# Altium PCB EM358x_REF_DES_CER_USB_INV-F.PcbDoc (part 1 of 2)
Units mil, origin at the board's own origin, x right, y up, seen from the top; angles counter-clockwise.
Board outline 2135 x 955 mil, 4 copper layers (Top Layer, Gnd Layer 2, Power Layer 3, Bottom Layer), stack 61.6 mil thick; 69 components, 52 nets, 241 pads, 167 vias.
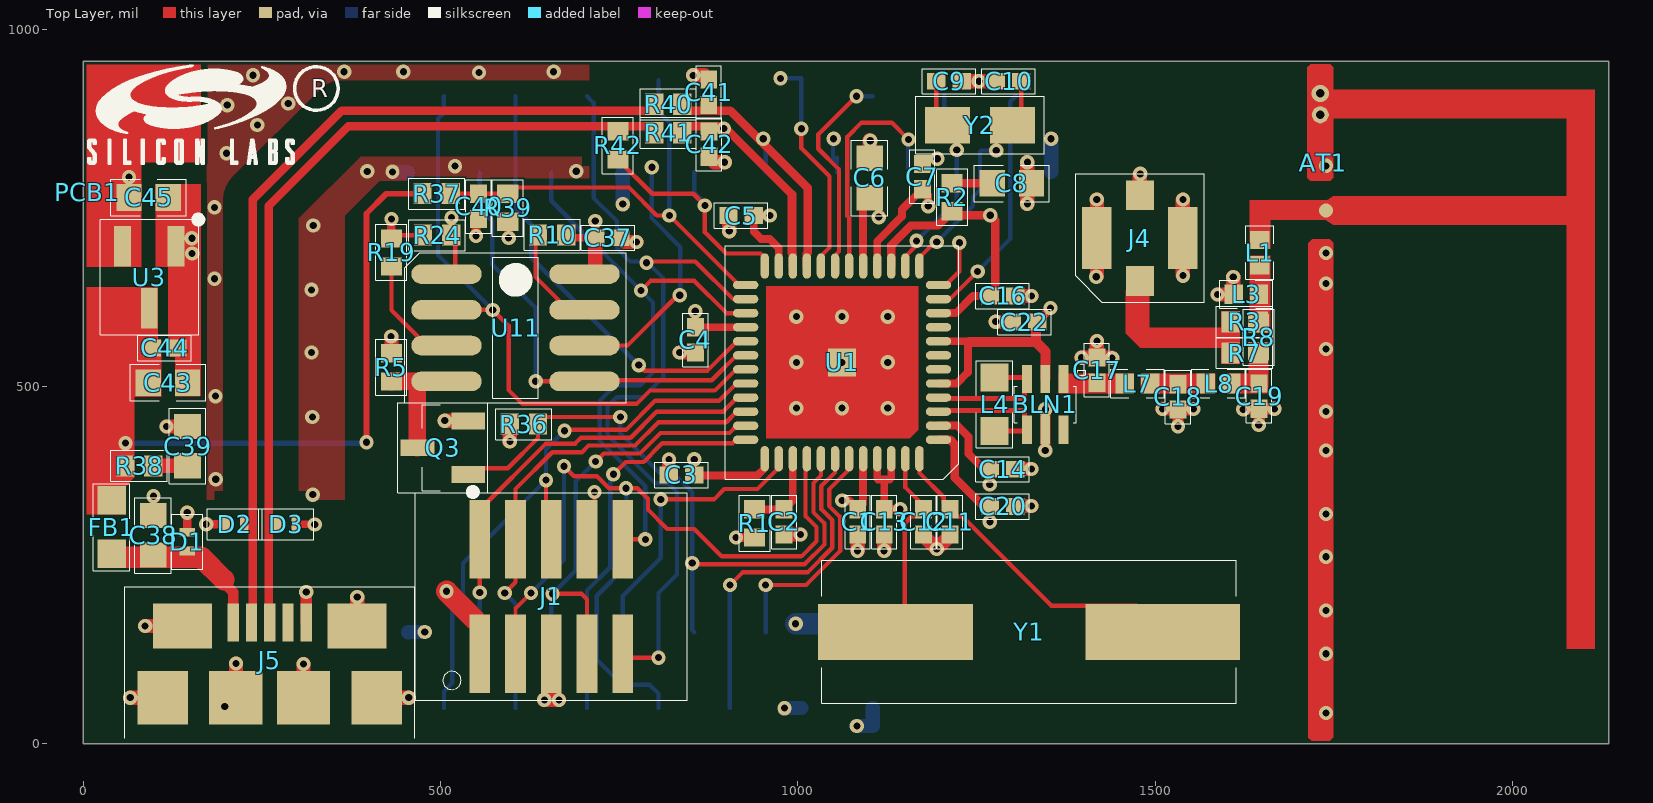
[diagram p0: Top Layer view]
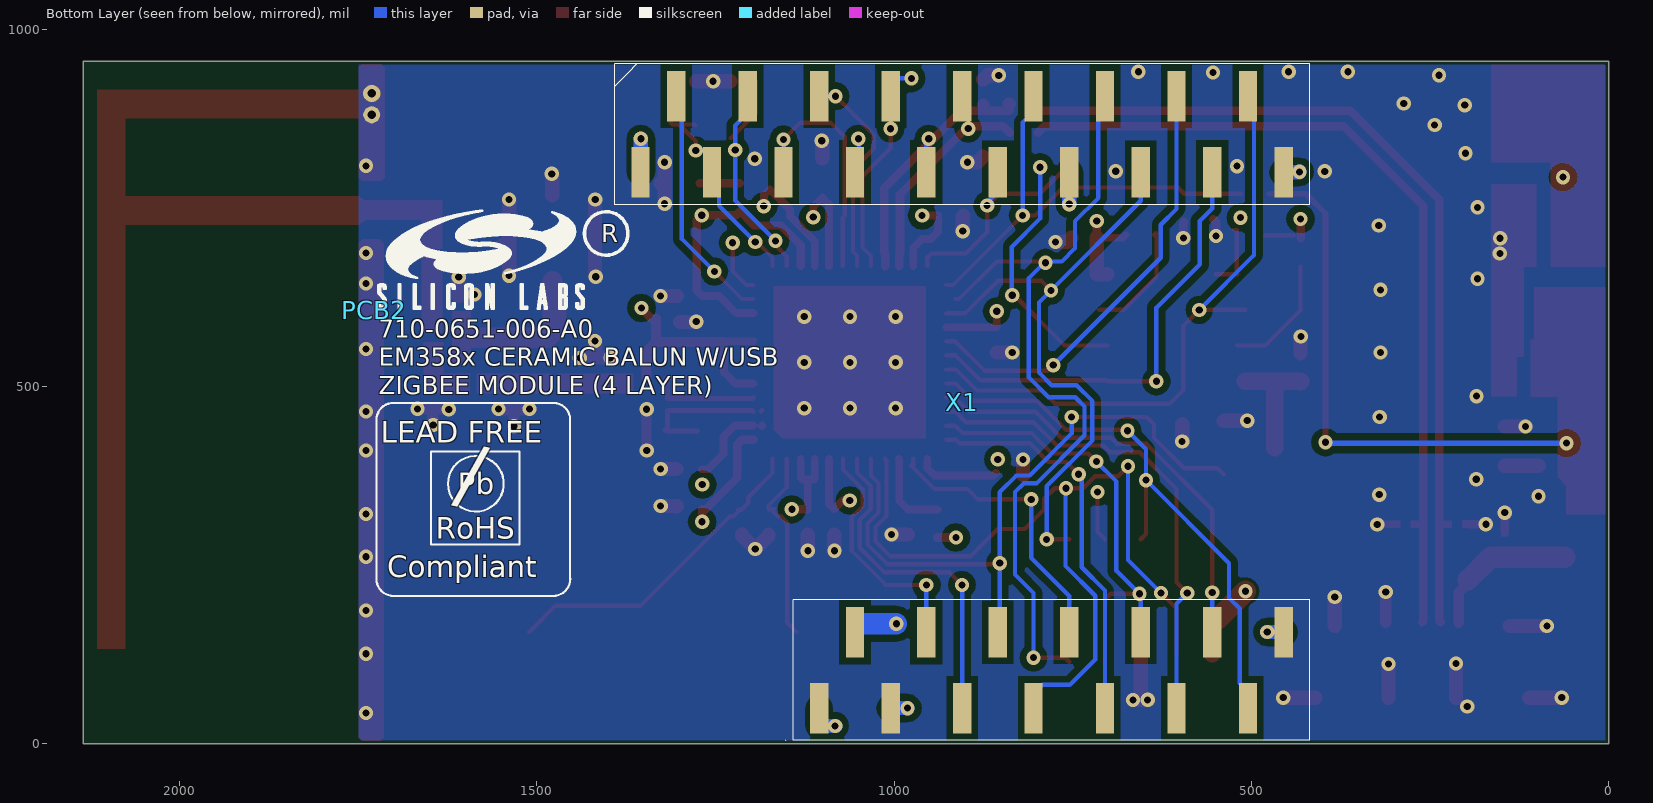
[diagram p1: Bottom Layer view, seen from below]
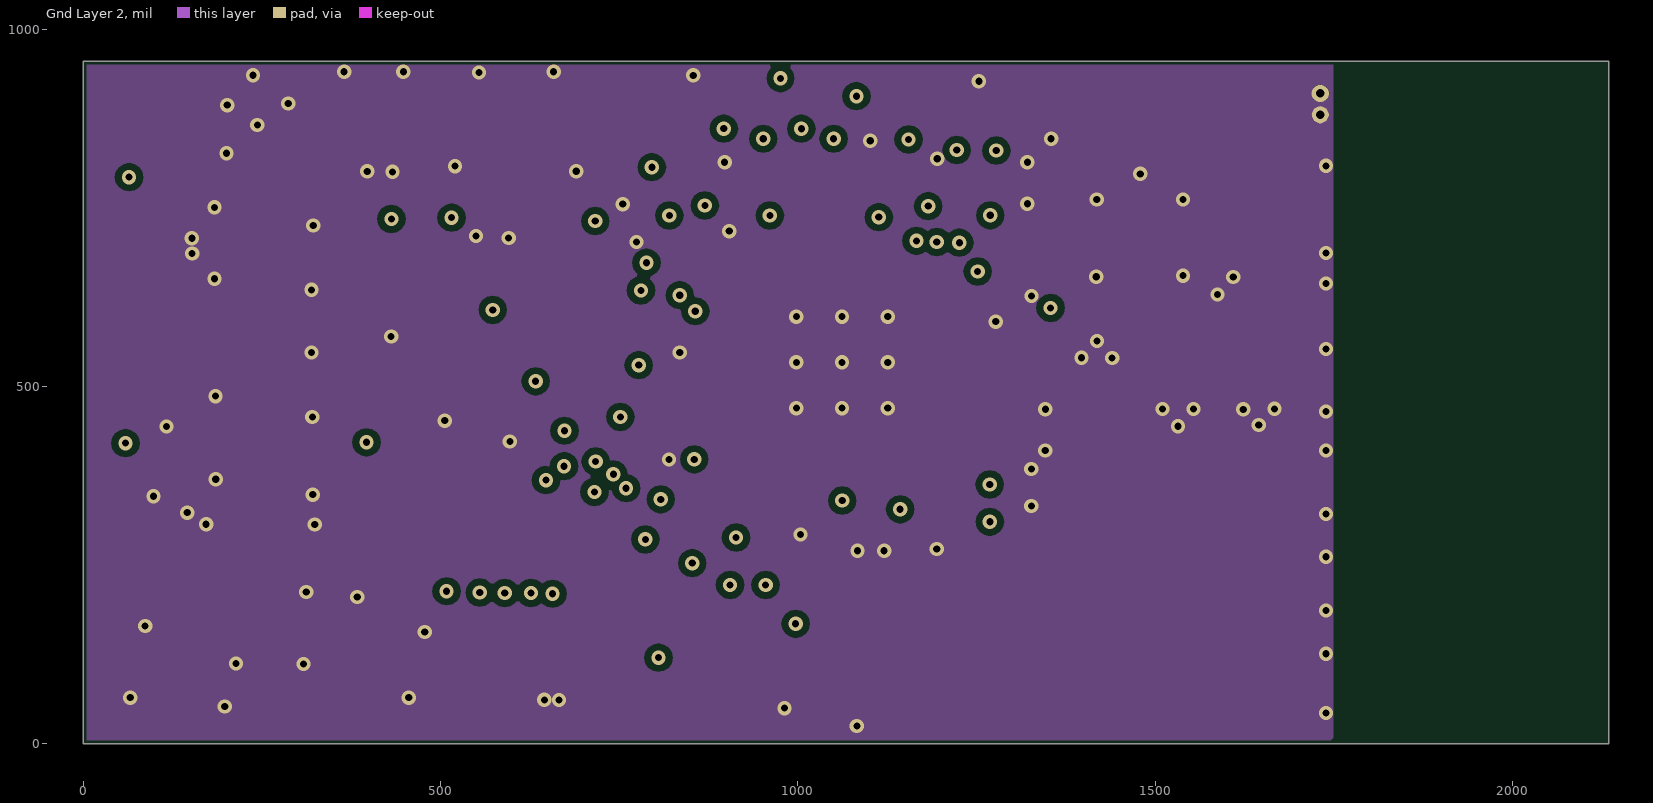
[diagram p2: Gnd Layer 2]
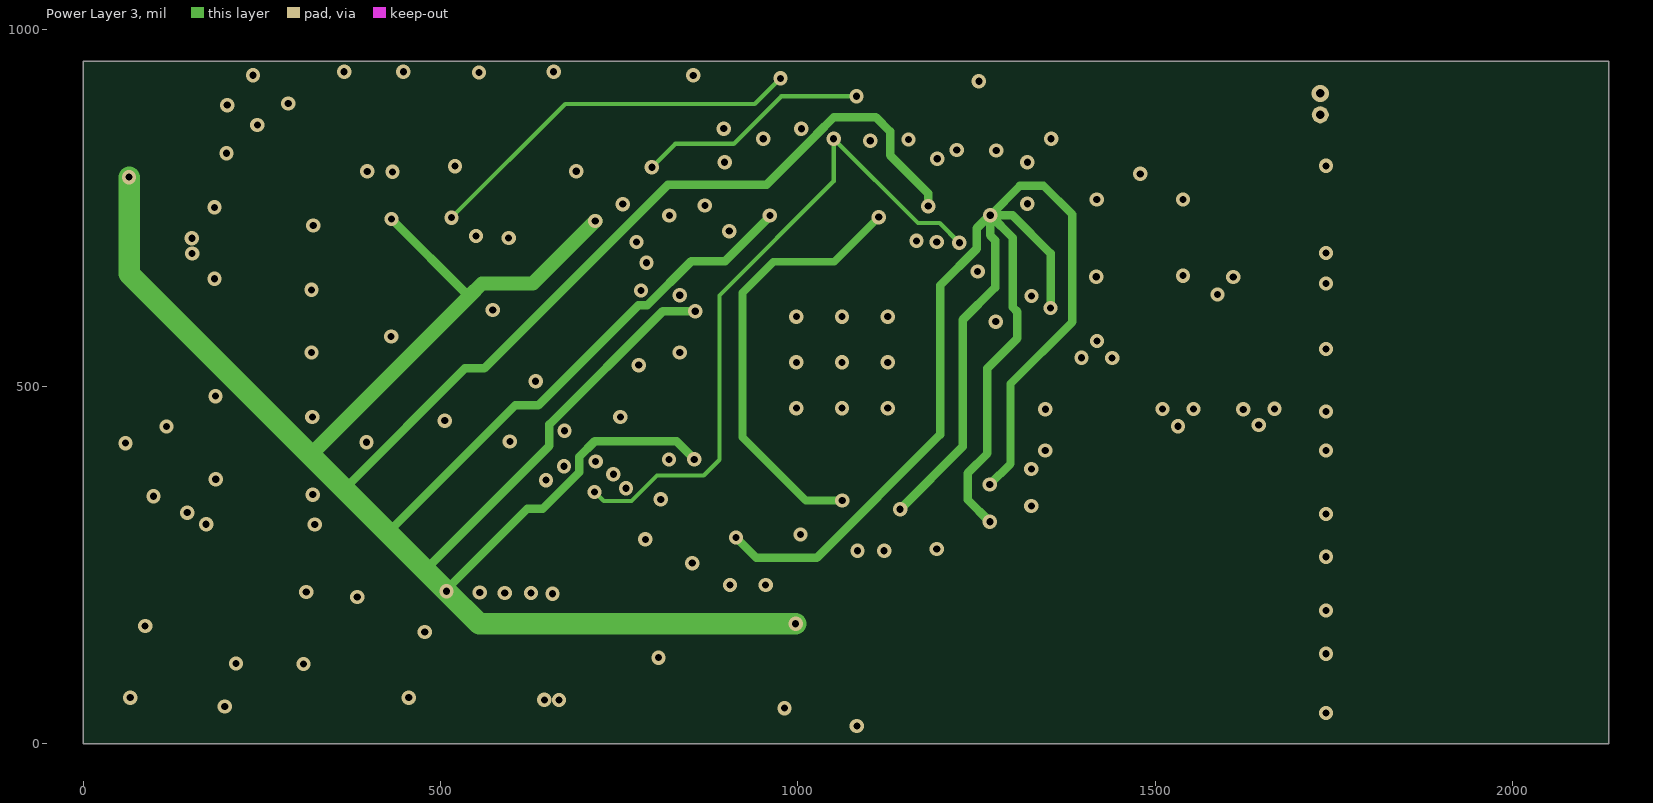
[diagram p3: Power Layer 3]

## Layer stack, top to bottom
Top Solder: solder mask 0.4, Solder Resist, Dk 3.5
Top Layer: signal copper 1.4
Dielectric1: prepreg 16, HR370, Dk 3.9
Gnd Layer 2: signal copper 1.4
Dielectric2: core 24, HR370, Dk 3.9
Power Layer 3: signal copper 1.4
Dielectric3: prepreg 16, HR370, Dk 3.9
Bottom Layer: signal copper 1.4
Bottom Solder: solder mask 0.4, Solder Resist, Dk 3.5

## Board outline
0,0 0,955 2135,955 2135,0

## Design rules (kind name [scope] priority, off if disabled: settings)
AssemblyTestpoint [All] p1: testpointundercomponent=TRUE minsize=30 maxsize=40 preferedsize=40 minholesize=0 maxholesize=10 preferedholesize=10 testpointgrid=1 usegrid=TRUE gridtolerance=0.01 allowsidetop=TRUE allowsidebottom=TRUE
Clearance "D_N - GND" [InNet('D_N') vs (InNet('GND') AND OnLayer('Top Layer') AND InNamedPolygon('USB Shield'))] p1: gap=36 // USB - GND
Clearance "D_P - GND" [InNet('D_P') vs (InNet('GND') AND OnLayer('Top Layer') AND InNamedPolygon('USB Shield'))] p2: gap=36 // USB - GND
Clearance PCB_Only [(InComponentClass('PCB Only')) vs InNet('GND')] p3: gap=0
Clearance "Schematic Clearance Constraint" [InNetClass('R7_Nets')] p4: gap=6
Clearance "Schematic Clearance Constraint_6" [InNet('GND')] p5: gap=9.5
Clearance "Schematic Clearance Constraint_5" [InNetClass('L1_Nets')] p6: gap=6
Clearance "Schematic Clearance Constraint_4" [InNetClass('L7_Nets')] p7: gap=6
Clearance "Schematic Clearance Constraint_3" [InNetClass('L8_Nets')] p8: gap=6
Clearance "Schematic Clearance Constraint_2" [InNetClass('R8_Nets')] p9: gap=6
Clearance "Schematic Clearance Constraint_1" [InNetClass('R3_Nets')] p10: gap=6
Clearance [All] p11: gap=5
ComponentClearance [All] p1: gap=0.1 collisioncheckmode=3 verticalgap=6 showdistances=TRUE
DiffPairsRouting "Schematic Differential Pairs Routing" [InNetClass('R40_Nets')] p1: maxlimit=50 minlimit=8 mostfreqgap=9 toplayer_minwidth=15 toplayer_maxwidth=15 toplayer_prefwidth=15 midlayer1_minwidth=15 midlayer1_maxwidth=15 midlayer1_prefwidth=15 midlayer2_minwidth=15 midlayer2_maxwidth=15 midlayer2_prefwidth=15 bottomlayer_minwidth=15 bottomlayer_maxwidth=15 bottomlayer_prefwidth=15 maxuncoupledlength=500
DiffPairsRouting "Schematic Differential Pairs Routing_1" [InNetClass('R41_Nets')] p2: maxlimit=50 minlimit=8 mostfreqgap=9 toplayer_minwidth=15 toplayer_maxwidth=15 toplayer_prefwidth=15 midlayer1_minwidth=15 midlayer1_maxwidth=15 midlayer1_prefwidth=15 midlayer2_minwidth=15 midlayer2_maxwidth=15 midlayer2_prefwidth=15 bottomlayer_minwidth=15 bottomlayer_maxwidth=15 bottomlayer_prefwidth=15 maxuncoupledlength=500
DiffPairsRouting [All] p3: maxlimit=10 minlimit=10 mostfreqgap=10 toplayer_minwidth=15 toplayer_maxwidth=15 toplayer_prefwidth=15 midlayer1_minwidth=15 midlayer1_maxwidth=15 midlayer1_prefwidth=15 midlayer2_minwidth=15 midlayer2_maxwidth=15 midlayer2_prefwidth=15 bottomlayer_minwidth=15 bottomlayer_maxwidth=15 bottomlayer_prefwidth=15 maxuncoupledlength=500
FabricationTestpoint [All] p1: side=3 testpointundercomponent=TRUE minsize=30 maxsize=40 preferedsize=40 minholesize=0 maxholesize=10 preferedholesize=10 testpointgrid=1 allowsidetop=TRUE allowsidebottom=TRUE usegrid=TRUE gridtolerance=0.01
HoleSize [All] p1: absolutevalues=TRUE maxlimit=100 minlimit=10 maxpercent=80.000 minpercent=20.000
MatchedLengths "Schematic Matched Net Lengths_2" [InNetClass('R40_Nets')] p1: tolerance=100 checknetsindiffpair=TRUE checkdiffpairvsdiffpair=FALSE checkothers=FALSE
MatchedLengths "Schematic Matched Net Lengths_1" [InNetClass('R41_Nets')] p2: tolerance=100 checknetsindiffpair=TRUE checkdiffpairvsdiffpair=FALSE checkothers=FALSE
MatchedLengths "Schematic Matched Net Lengths" [InNetClass('L4_Nets')] p3: tolerance=2.5 checknetsindiffpair=TRUE checkdiffpairvsdiffpair=FALSE checkothers=FALSE
MinimumSolderMaskSliver [All] p1: minsoldermaskwidth=2
PlaneClearance [All] p1: clearance=10
PlaneConnect [All] p1: planeconnectstyle=Direct reliefexpansion=20 reliefentries=4 reliefconductorwidth=10 reliefairgap=10
PolygonConnect PolygonConnect_4 [All vs IsNamedPolygon('Top Layer-No Net')] p1: connectstyle=Relief reliefconductorwidth=10 reliefentries=4 polygonreliefangle="90 Angle" airgapwidth=10
PolygonConnect PolygonConnect_3 [All vs IsNamedPolygon('GROUND')] p2: connectstyle=Direct reliefconductorwidth=10 reliefentries=4 polygonreliefangle="90 Angle" airgapwidth=10
PolygonConnect PolygonConnect_2 [All vs IsNamedPolygon('GROUND')] p3: connectstyle=Direct reliefconductorwidth=10 reliefentries=4 polygonreliefangle="90 Angle" airgapwidth=10
PolygonConnect PolygonConnect_1 [All vs IsNamedPolygon('GROUND')] p4: connectstyle=Relief reliefconductorwidth=10 reliefentries=4 polygonreliefangle="90 Angle" airgapwidth=10
PolygonConnect [All] p5: connectstyle=Direct reliefconductorwidth=10 reliefentries=4 polygonreliefangle="90 Angle" airgapwidth=10
RoutingVias [All] p1: holewidth=10 width=20 viastyle="Through Hole" minholewidth=10 minwidth=20 maxholewidth=10 maxwidth=40
ShortCircuit ShortCircuit_1 [InNet('NetAT1_1') vs InNet('GND')] p1: allowed=TRUE
ShortCircuit [All] p2: allowed=FALSE
ShortCircuit "Schematic Short-Circuit Constraint" [InNet('GND')] p3: allowed=TRUE
SilkToSilkClearance SilkToSilkClearance_1 [(InComponentClass('PCB Only')) vs (InComponentClass('PCB Only'))] p1: silktosilkclearance=0
SilkToSilkClearance SilkToSilkClearance_2 [InComponent('U11')] p2: silktosilkclearance=0
SilkToSilkClearance [All] p3: silktosilkclearance=0.1
SilkToSolderMaskClearance SilkscreenOverComponentPads [IsPad] p1: minsilkscreentomaskgap=0.1 clearancetoexposedcopper=TRUE
SolderMaskExpansion [All] p1: expansion=1
Width "Schematic Width Constraint_2" [InNetClass('R40_Nets')] p1: maxlimit=60 minlimit=6 preferedwidth=12
Width "Schematic Width Constraint_3" [InNetClass('R41_Nets')] p2: maxlimit=60 minlimit=6 preferedwidth=12
Width "Schematic Width Constraint_1" [InNetClass('R7_Nets')] p3: maxlimit=60 minlimit=6 preferedwidth=28
Width "Schematic Width Constraint_14" [InNetClass('C22_Nets')] p4: maxlimit=40 minlimit=5 preferedwidth=20
Width "Schematic Width Constraint_13" [InNetClass('C6_Nets')] p5: maxlimit=40 minlimit=5 preferedwidth=20
Width "Schematic Width Constraint_12" [InNetClass('C45_Nets')] p6: maxlimit=40 minlimit=5 preferedwidth=20
Width "Schematic Width Constraint_11" [InNetClass('L1_Nets')] p7: maxlimit=60 minlimit=6 preferedwidth=28
Width "Schematic Width Constraint_10" [InNetClass('L7_Nets')] p8: maxlimit=60 minlimit=6 preferedwidth=28
Width "Schematic Width Constraint_9" [InNetClass('L8_Nets')] p9: maxlimit=60 minlimit=6 preferedwidth=28
Width "Schematic Width Constraint_8" [InNetClass('R8_Nets')] p10: maxlimit=60 minlimit=6 preferedwidth=28
Width "Schematic Width Constraint_7" [InNetClass('R3_Nets')] p11: maxlimit=60 minlimit=6 preferedwidth=28
Width "Schematic Width Constraint" [InNetClass('L4_Nets')] p12: maxlimit=10 minlimit=5 preferedwidth=7
Width [All] p13: maxlimit=40 minlimit=4 preferedwidth=5
18 further rules are at their usual default settings.

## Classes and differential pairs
net class R39_Nets: GND PA3
net class R38_Nets: NetC39_1 VBUS
net class D1_Nets: GND NetC38_1
net class C43_Nets: GND VBUS
net class C39_Nets: GND NetC39_1
net class C38_Nets: GND NetC38_1
net class Y2_Nets: PC6 PC7
net class Y1_Nets: OSCA OSCB
net class X1_Nets: GND JCLK NRESET PA01_D_N PA01_D_P PA2 PA3 PA4 PA5 PA6 PA7 PB0 PB1 PB2 PB3 PB4 PB5 PB6 PB7 PC0 PC1 PC2 PC3 PC4 PC5 PC6 PC7 VBRD
net class U11_Nets: NSF_GND NSF_HOLD NSF_WP PB1 PB2 PB3 PB4 VBRD
net class U3_Nets: GND NetU3_4 VBRD VBUS
net class U1_Nets: 1V2_CORE 1V8 GND JCLK NetC2_1 NetU1_9 NRESET OSCA OSCB PA01_D_N PA01_D_P PA2 PA3 PA4 PA5 PA6 PA7 PB0 PB1 PB2 PB3 PB4 PB5 PB6 PB7 PC0 PC1 PC2 PC3 PC4 PC5 PC6 PC7 RF_N RF_P TX_ALT_N TX_ALT_P VBRD
net class C44_Nets: GND VBUS
net class R42_Nets: D_P PA2
net class R41_Nets: D_P PA01_D_P
net class R40_Nets: D_N PA01_D_N
net class C40_Nets: GND PA3
net class R37_Nets: PA3 VBUS
net class R36_Nets: GND PB7
net class R24_Nets: PB4 VBRD
net class R19_Nets: NSF_WP VBRD
net class R10_Nets: NSF_HOLD VBRD
net class R8_Nets: NetC19_1 NetL1_1
net class R7_Nets: NetC19_1 NetJ4_1
net class R5_Nets: GND NSF_GND
net class R3_Nets: NetJ4_1 NetL1_1
net class R2_Nets: 1V8 NetC8_1
net class R1_Nets: 1V8 NetC2_1
net class Q3_Nets: GND NSF_GND PB7
net class L8_Nets: NetC18_1 NetC19_1
net class L7_Nets: NetBLN1_1 NetC18_1
net class L4_Nets: RF_N RF_P
net class L3_Nets: GND NetL1_1
net class L1_Nets: NetAT1_1 NetL1_1
net class J5_Nets: D_N D_P GND NetC38_1 NetJ5_4
net class J4_Nets: GND NetJ4_1
net class J1_Nets: GND JCLK NRESET PA4 PA5 PC0 PC2 PC3 PC4 VBRD
net class FB1_Nets: NetC38_1 VBUS
net class D3_Nets: D_P GND
net class D2_Nets: D_N GND
net class C45_Nets: GND VBRD
net class C42_Nets: GND PA01_D_P
net class C41_Nets: GND PA01_D_N
net class C37_Nets: GND VBRD
net class C22_Nets: 1V8 GND
net class C20_Nets: 1V8 GND
net class C19_Nets: GND NetC19_1
net class C18_Nets: GND NetC18_1
net class C17_Nets: GND NetBLN1_1
net class C16_Nets: 1V8 GND
net class C14_Nets: 1V8 GND
net class C13_Nets: 1V8 GND
net class C12_Nets: GND OSCB
net class C11_Nets: GND OSCA
net class C10_Nets: GND PC6
net class C9_Nets: GND PC7
net class C8_Nets: GND NetC8_1
net class C7_Nets: GND VBRD
net class C6_Nets: 1V2_CORE GND
net class C5_Nets: GND VBRD
net class C4_Nets: GND VBRD
net class C3_Nets: GND VBRD
net class C2_Nets: GND NetC2_1
net class C1_Nets: 1V2_CORE GND
net class BLN1_Nets: 1V8 GND NetBLN1_1 NetBLN1_6 RF_N RF_P
net class AT1_Nets: GND NetAT1_1
component class "PCB Only": AT1 PCB1 PCB2
differential pair D: +D_P -D_N
differential pair PA01_D: +PA01_D_P -PA01_D_N
differential pair RF: +RF_P -RF_N

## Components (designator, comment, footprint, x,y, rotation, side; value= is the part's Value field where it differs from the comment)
AT1 "Copper Trace" INVERTED_F_062_SM 1749.2,746 r90 top
BLN1 "CHIP MULTILAYER CERAMIC, 2.4 GHZ. 50/100 Ohm" BLN_0805 1372,510 r0 top
C1 "10NF" C_0402 1084,328 r180 top
C2 "0.47uF" C_0402 981,328 r180 top
C3 "0.1uF" C_0402 855,376 r90 top
C4 "0.1uF" C_0402 856.8,582.7 r180 top
C5 "0.1uF" C_0402 938.4,738.9 r90 top
C6 "1.0uF" C_0603 1100.6,764 r90 top
C7 "0.1uF" C_0402 1174.3,775.76 r0 top
C8 "2.2uF" C_0603 1272,784 r0 top
C9 "33pF, (DNI)" C_0402 1193.99,926.94 r270 top
C10 "22PF, (DNI)" C_0402 1312.87,926.94 r90 top
C11 "22PF" C_0402 1213,328 r180 top
C12 "22PF" C_0402 1176,328 r180 top
C13 "10pF" C_0402 1121,328 r180 top
C14 "10NF" C_0402 1269,384 r270 top
C16 "10NF" C_0402 1269,626.5 r270 top
C17 "1pF" C_0402 1418.5,504.9 r0 top
C18 "1.8pF" C_0402 1532.1,502.9 r180 top
C19 "1pF" C_0402 1645.6,503.9 r180 top
C20 "10NF" C_0402 1269,332 r270 top
C22 "10pF" C_0402 1335,590 r90 top
C37 "10NF, (DNI)" C_0402 716.62,707.87 r270 top
C38 "1.0uF" C_0603 98,264 r90 top
C39 "4.7uF" C_0603 146.07,388.76 r90 top
C40 "1.0uF, (DNI)" C_0402 553.4,769.49 r180 top
C41 "33pF" C_0402 875.5,893.8 r0 top
C42 "33pF" C_0402 876,856.5 r180 top
C43 "DNI" C_0603 90.95,505.03 r0 top
C44 "10NF, (DNI)" C_0402 96.35,553.65 r270 top
C45 "1.0uF, (DNI)" C_0603 64.01,764.3 r0 top
D1 "TVS" TVS_0402 145.63,282.5 r270 top (schematic designator D2)
D2 "TVS" TVS_0402 212.4,307 r0 top
D3 "TVS" TVS_0402 284.4,307 r180 top
FB1 "60Ohm 100MHz" L_0603 40,265.67 r180 top
J1 "FTSH-105-01-F-DV-K, (DNI)" 610-0019-000-REF-DES 555,126 r270 top
J4 "U.FL, (DNI)" UFL-R-SMT_1 1478.7,707.4 r180 top
J5 "10118192-0001LF" FCI_10118192-0001LF 261.07,169.61 r0 top
L1 "2.0nH" L_0402 1646.4,669.36 r90 top
L3 "1.5nH" L_0402 1645.4,628.7 r180 top
L4 "3.9nH" L_0603 1275.5,512.3 r0 top
L7 "2.7nH" L_0402 1457.66,503.9 r0 top
L8 "2.7nH" L_0402 1571.1,503.9 r0 top
LOGO1 "SiliconLabsLogo_100" SiliconLabsLogo_100_Mech-16 3677,-1889.5 r0 top
PCB1 "EM35x Ceramic Balun 4 Layer Reference Design w/USB, Inverted F, Corporate Logo" 710-0651-006 5.5,771.4 r0 top
PCB2 "Bottom Silk Screen ID and RoHS Text" 710-0651-006_ROHS 1727.5,606.7 r180 bottom
Q3 "2N7002, (DNI)" SOT23-3L 503.4,414.1 r180 top
R1 "10 Ohm" R_0402 939.7,288.4 r90 top
R2 "1 Ohm" R_0402 1216,745 r90 top
R3 "0_OHM, (DNI)" R_0402 1645,590.1 r180 top
R5 "0_OHM, (DNI)" R_0402 431.4,506.7 r90 top
R7 "0_OHM, (DNI)" R_0402 1645,546.6 r180 top
R8 "0_OHM" R_0402 1645,548.73 r90 top
R10 "100K, (DNI)" R_0402 636.57,711.94 r0 top
R19 "100K, (DNI)" R_0402 431.4,667.63 r90 top
R24 "100K, (DNI)" R_0402 515,711.5 r180 top
R36 "100K, (DNI)" R_0402 636.37,447 r180 top
R37 "100K" R_0402 474.97,769.58 r0 top
R38 "0.51 ohm" R_0402 98.11,388.76 r180 top
R39 "150K" R_0402 594.1,769.58 r270 top
R40 "33 Ohm" R_0402 799,894.75 r0 top
R41 "33 Ohm" R_0402 799,854.78 r0 top
R42 "1.5k" R_0402 748.21,856.81 r270 top
U1 "EM358x" EM357 1062,533.5 r0 top
U3 "LDO, (DNI)" TSOP95P280X90-3N 92.5,652.65 r270 top
U11 "8M, (DNI)" SOIC127P600-8M 605,582 r0 top
X1 "Dual Row Socket, (DNI)" EM35X_RCM_MODULE_SIDE_SMT 1355,852.85 r180 bottom locked
Y1 "24.000MHZ, 18PF LOAD" HC-49-SMD 1323.73,156.33 r180 top
Y2 "32.768KHz, 12.5pF, (DNI)" IL3X 1254.93,865.44 r180 top

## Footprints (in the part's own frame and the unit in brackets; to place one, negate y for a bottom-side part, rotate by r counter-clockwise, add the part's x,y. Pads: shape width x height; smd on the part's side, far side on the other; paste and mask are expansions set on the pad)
610-0019-000-REF-DES [mil] "old footprint with keepout for cable connector"
  rect 110x29 smd: 1(0,0) 2(-160,0) 3(0,50) 4(-160,50) 5(0,100) 6(-160,100) 7(0,150) 8(-160,150) 9(0,200) 10(-160,200)
  silkscreen extent -225,-90 65,290, body extent -148,-25 -12,225, height 225
710-0651-006 [mil] "EM35x Ceramic Balun W/USB W/Inverted F"
  silkscreen extent 1,40 351,178
710-0651-006_ROHS [mil] "EM35x CERAMIC BALUN W/USB W/Inverted F"
  silkscreen extent 3,-400 355,139
BLN_0805 [mm]
  rect 0.35x1 smd: 1(0,0) 2(-0.65,0) 3(-1.3,0) 4(-1.3,-1.8) 5(-0.65,-1.8) 6(0,-1.8)
  silkscreen extent -1.75,-1.55 0.78,0.31
C_0402 [mm]
  rect 0.6x0.65 smd mask+0.051: 1(0,0) 2(0,0.9)
  silkscreen extent -0.45,-0.5 0.45,1.4, body extent -0.28,-0.05 0.28,0.97, height 1.02
C_0603 [mm]
  rect 0.9x0.95 smd mask+0.051: 1(0,0) 2(1.4,0)
  silkscreen extent -0.64,-0.65 2.04,0.65, body extent -0.09,-0.39 1.51,0.39, height 0.89
EM35X_RCM_MODULE_SIDE_SMT [mm]
  rect 0.65x1.8 smd: 1(0,-1.35) 2(1.27,1.35) 3(2.54,-1.35) 4(3.81,1.35) 5(5.08,-1.35) 6(6.35,1.35) 7(7.62,-1.35) 8(8.89,1.35) 9(10.16,-1.35) 10(11.43,1.35) 11(12.7,-1.35) 12(13.97,1.35) 13(15.24,-1.35) 14(16.51,1.35) 15(17.78,-1.35) 16(19.05,1.35) 17(20.32,-1.35) 18(21.59,1.35) 19(22.86,-1.35) 20(22.86,-17.7) 21(21.59,-20.4) 22(20.32,-17.7) 23(19.05,-20.4) 24(17.78,-17.7) 25(16.51,-20.4) 26(15.24,-17.7) 27(13.97,-20.4) 28(12.7,-17.7) 29(11.43,-20.4) 30(10.16,-17.7) 31(8.89,-20.4) 32(7.62,-17.7) 33(6.35,-20.4)
  silkscreen extent -0.93,-21.56 23.78,2.5
EM357 [mm]
  oval 0.9x0.3 smd paste+0 mask+0: 1(3.425,-2.75) 2(3.425,-2.25) 3(3.425,-1.75) 4(3.425,-1.25) 5(3.425,-0.75) 6(3.425,-0.25) 7(3.425,0.25) 8(3.425,0.75) 9(3.425,1.25) 10(3.425,1.75) 11(3.425,2.25) 12(3.425,2.75) 25(-3.425,2.75) 26(-3.425,2.25) 27(-3.425,1.75) 28(-3.425,1.25) 29(-3.425,0.75) 30(-3.425,0.25) 31(-3.425,-0.25) 32(-3.425,-0.75) 33(-3.425,-1.25) 34(-3.425,-1.75) 35(-3.425,-2.25) 36(-3.425,-2.75)
  oval 0.3x0.9 smd paste+0 mask+0: 13(2.75,3.425) 14(2.25,3.425) 15(1.75,3.425) 16(1.25,3.425) 17(0.75,3.425) 18(0.25,3.425) 19(-0.25,3.425) 20(-0.75,3.425) 21(-1.25,3.425) 22(-1.75,3.425) 23(-2.25,3.425) 24(-2.75,3.425) 37(-2.75,-3.425) 38(-2.25,-3.425) 39(-1.75,-3.425) 40(-1.25,-3.425) 41(-0.75,-3.425) 42(-0.25,-3.425) 43(0.25,-3.425) 44(0.75,-3.425) 45(1.25,-3.425) 46(1.75,-3.425) 47(2.25,-3.425) 48(2.75,-3.425)
  rect 1x1 smd paste-1 mask+0: 49(0,0)
  Top Layer region: 2.7,-2.4 2.4,-2.7 -2.7,-2.7 -2.7,2.7 2.7,2.7
  Top Layer pour cut-out: 3.506,-3.505 3.046,-3.505 3.046,-3.045 3.506,-3.045 3.506,-3.505
  Top Layer pour cut-out: 3.507,3.04 3.047,3.04 3.047,3.5 3.507,3.5 3.507,3.04
  Top Layer pour cut-out: -3.039,3.04 -3.499,3.04 -3.499,3.5 -3.039,3.5 -3.039,3.04
  Top Layer pour cut-out: -3.039,-3.503 -3.499,-3.503 -3.499,-3.043 -3.039,-3.043 -3.039,-3.503
  silkscreen extent -4.15,-4.15 4.15,4.15, body extent -3.51,-3.51 3.51,3.51, height 0.9
FCI_10118192-0001LF [mm] "USB Connector - Surface Mount"
  rect 0.4x1.35 smd mask+0.076: 1(-1.3,0) 2(-0.65,0) 3(0,0) 4(0.65,0) 5(1.3,0)
  rect 2.1x1.6 smd mask+0.076: 6(3.1,-0.125) 11(-3.1,-0.125)
  rect 1.8x1.9 smd mask+0.076: 7(3.8,-2.675) 10(-3.8,-2.675)
  rect 1.9x1.9 smd mask+0.076: 8(1.2,-2.675) 9(-1.2,-2.675)
  silkscreen extent -5.15,-4.13 5.15,1.26, body extent -4.16,-5.69 4.16,0.35, height 3
HC-49-SMD [mm]
  rect 5.5x2 smd: 1(-4.75,0) 2(4.75,0)
  silkscreen extent -7.37,-2.54 7.37,2.54, body extent -7.24,-2.41 7.24,2.41, height 4.06
IL3X [mil]
  rect 62.99x51.18 smd: 1(-45.28,0) 2(45.28,0)
  silkscreen extent -90,-40 90,40, body extent -63,-30 63,30, height 36
INVERTED_F_062_SM [mil]
  round 20 smd paste-20 mask-20: 1(0,10)
  round 24 hole 12 paste-24 mask+1: 2(134,18)
  Top Layer region: 116,36 182,36 182,0 116,0 116,36
  Top Layer region: -613,-327 169,-327 169,-366 -613,-366 -613,-327
  Top Layer region: -20,0 20,0 20,-327 -20,-327 -20,0
  Top Layer region: 129,0 169,0 169,-327 129,-327 129,0
  Top Layer region: -7,20 7,20 20,0 -20,0 -7,20
  Multi-Layer pour cut-out: -746,0 209,0.01 209,-386 -746,-386 -746,0
L_0402 [mm]
  rect 0.65x0.7 smd: 1(0,0) 2(0.9,0)
  silkscreen extent -0.5,-0.5 1.4,0.5, body extent -0.06,-0.28 0.95,0.28, height 1.02
L_0603 [mm]
  rect 1x1 smd: 1(0,0) 2(0,-1.9)
  silkscreen extent -0.65,-2.5 0.65,0.6, body extent -0.39,-1.74 0.39,-0.14, height 0.89
R_0402 [mm]
  rect 0.65x0.75 smd: 1(0,0) 2(1,0)
  silkscreen extent -0.5,-0.55 1.5,0.55, body extent -0.01,-0.28 1,0.28, height 1.02
SiliconLabsLogo_100_Mech-16 [mil] "Silicon Labs Logo for Sheet Layer"
SOIC127P600-8M [mm] "SOIC, 8-Leads, Body 4.9x3.9mm, Pitch 1.27mm, IPC Low Density"
  oval 2.5x0.7 smd: 1(-2.45,1.905) 2(-2.45,0.635) 3(-2.45,-0.635) 4(-2.45,-1.905) 5(2.45,-1.905) 6(2.45,-0.635) 7(2.45,0.635) 8(2.45,1.905)
  silkscreen extent -3.94,-2.67 3.94,2.67, body extent -2,-2.5 2,2.5, height 1.75
SOT23-3L [mm] "SOT23, 3-Leads, Body 2.9x1.3mm, Pitch 0.95mm, Lead Span 2.5mm, IPC High Density"
  rect 1.2x0.6 smd: 1(-0.9,0.95) 2(-0.9,-0.95) 3(0.9,0)
  silkscreen extent -1.6,-1.6 1.6,1.7, body extent -0.7,-1.5 0.7,1.5, height 1.1
TSOP95P280X90-3N [mm] "SC59, Skyworks TSOP, 3-Leads, Body 2.85x1.53mm, Pitch 0.95mm, IPC Medium Density"
  rect 1.45x0.6 smd: 1(-1.1,0.95) 2(-1.1,-0.95) 3(1.1,0)
  silkscreen extent -2.17,-1.75 2.05,1.87, body extent -0.8,-1.5 0.8,1.5, height 1.5
TVS_0402 [mil] "TVS_DIODE_0402"
  rect 12x22 smd mask+2: 1(-13,0) 2(13,0)
  Top Layer region: 7,-5 31,-5 31,5 7,5
  Top Layer region: -31,-5 -7,-5 -7,5 -31,5
  silkscreen extent -39,-22 39,22, body extent -20,-12 20,12, height 40
UFL-R-SMT_1 [mm]
  rect 1x1.05 smd: 1(0,1.525) 4(0,-1.525)
  rect 1.05x2.2 smd: 2(-1.525,0) 3(1.525,0)
  silkscreen extent -2.29,-2.29 2.29,2.29

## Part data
AT1: library part 600-0PCB-ANT-F-62, "Inverted F Antenna"
BLN1: library part 566-0075-000, "Balun 0805"
C1 C14 C16 C20: library part 550-0036-000
C2: library part 550-0037-000
C3 C4 C5 C7: library part 550-0034-000
C6: library part 550-0033-000
C8: library part 550-0038-000
C9: library part 550-0039-000-DNI
C10: library part 550-2201-050-DNI
C11 C12: library part 550-2201-050
C13 C22: library part 550-1001-050
C17 C19: library part 550-0040-000
C18: library part 550-1P8A-050
C37: library part 550-0036-000-DNI
C38 C39: library part 550-0039-000
C40 C45: library part 550-0033-000-DNI
C41 C42: library part 550-3301-050
C43: library part 550-0603-DNI
C44: library part 550-0035-000-DNI
D1 D2 D3: library part 545-0062-000
FB1: library part 566-0001-000, "*"
J1: library part 610-0045-000-DNI, "CONNECTOR, HEADER, SHROUDED, 10 POSITION, DUAL ROW, VERTICAL, 0.050\""
J4: library part 610-0081-000-DNI, "U.FL RF Coaxial Connector"
J5: library part 610-0105-000
L1: library part 566-2N0A-000, "Design Placeholder"
L3: library part 566-1N5A-000, "Design Placeholder"
L4: library part 566-3N9S-000, "Design Placeholder"
L7 L8: library part 566-2N7W-000, "Design Placeholder"
LOGO1: "Company Logo in PCB Title Block"
PCB1: library part 710-0651-006, "PCB BoM ID and Top Side Silk Screen Identifier"
PCB2: library part 710-0651-006_ROHS, "Bottom Side Silk Screen Identifier"
Q3: library part 545-0047-000-DNI, "MOSFET N-Channel"
R1: library part 555-1001-010
R2: library part 555-1R05-016
R3 R5 R7: library part 555-0000-000-DNI
R8: library part 555-0000-000
R10 R19 R24 R36: library part 555-1045-016-DNI
R37: library part 555-1045-016
R38: library part 555-0017-000
R39: library part 555-150K-016
R40 R41: library part 555-33R1-010
R42: library part 555-1521-016
U1: library part 540-0358-000, "IC, EM357, ZIGBEE/802.15.4 RF SOLUTION, ARM CORTEX-M3, 12K RAM, 192K FLASH, QFN-48"
U3: library part 500-0089-000-DNI
U11: library part 510-1039-000-DNI, "IC - MEMORY, SERIAL FLASH, 2M (2M X 1, 1M X 2), 2.7 V - 3.6 V, -40C  85C, 8-SOIC (0.154\", 3.90MM WIDTH)"
X1: library part 610-0010-DNI, "610-0010-DNI"
Y1: library part 565-2400-009, "OSCILLATOR, CRYSTAL, 24.000MHZ, 18PF LOAD, +/-10PPM TOLERANCE, +/-25PPM STABILITY, -40C TO 85C, AT49"
Y2: library part 565-3271-001-DNI

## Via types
v1: diameter 20, hole 10, Top Layer to Bottom Layer, 166 vias
v2: diameter 24, hole 12, Top Layer to Bottom Layer, 1 vias

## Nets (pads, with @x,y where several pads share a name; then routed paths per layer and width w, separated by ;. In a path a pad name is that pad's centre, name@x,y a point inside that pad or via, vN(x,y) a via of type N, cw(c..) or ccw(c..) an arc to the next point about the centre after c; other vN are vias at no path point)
1V2_CORE: C1.1 C6.1 U1.17 U1.44 | length 845.7
  Top Layer w11: v1(1062.2,340.1) 1071.9,340.1 C1.1@1084,328 1091.43,335.43 1091.53,335.43 U1.44@1091.53,398.66 ; U1.17@1091.53,668.34 1091.53,754.93 C6.1@1100.6,764 1113.4,751.2 v1(1113.4,736.7)
  Power Layer 3 w11: v1(1062.2,340.1) 1011.3,340.1 922.6,428.8 922.6,630.9 966.1,674.4 1051.1,674.4 v1(1113.4,736.7)
1V8: BLN1.2 C13.1 C14.1 C16.1 C20.1 C22.1 R1.1 R2.1 U1.1 U1.2 U1.5 U1.8 U1.10 U1.15 U1.45 U1.46 | length 3586.2
  Top Layer w11: U1.45@1111.21,398.66 1111.21,370.79 1112.5,369.5 1120.4,369.5 ; C13.1@1121,328 1121,368.9 1120.4,369.5 ; U1.46@1130.9,398.66 1130.9,372.04 1128.36,369.5 1120.4,369.5 ; U1.2@1184.84,444.92 U1.2@1185.26,444.5 ; U1.2@1196.84,444.92 1223.58,444.92 1239,429.5 1239,405.7 1260.7,384 C14.1@1268.8,384 ; U1.5@1196.84,503.97 1222.47,503.97 1238,519.5 1238,563.03 U1.8@1196.84,563.03 ; U1.10@1196.84,602.4 1220.9,602.4 1245,626.5 C16.1@1267.56,626.5
  Top Layer w11.5: U1.15@1130.9,668.34 1130.9,697.74 1158.26,725.1 1196.1,725.1 R2.1@1216,745 1221.7,739.3 v1(1269.4,739.3) 1276.4,732.3 1276.4,644.63 1276.39,633.89 C16.1@1269,626.5
  Top Layer w12: v1(913.7,288.4) R1.1@939.7,288.4 ; C13.1@1121,328 1121.1,327.9 v1(1143.3,327.9) ; U1.1@1196.84,425.23 1213.27,425.23 1219.5,419 1219.5,372.3 1263.6,328.2 1268.8,328.2 v1(1268.8,310.4) ; C22.1@1335,590 1353.8,608.8 v1(1353.8,609.7)
  Top Layer w14: 1239.34,561.69 1333.66,561.69 ; C22.1@1333.66,594.98 1333.66,561.69 ; BLN1.2@1346.41,510 1346.41,548.94 1333.66,561.69
  Power Layer 3 w11.5: v1(1268.6,362.6) 1297.6,391.6 1297.6,503.6 1384.2,590.2 1384.2,740.3 1343.85,780.65 1310.75,780.65 v1(1269.4,739.3)
  Power Layer 3 w12: v1(913.7,288.4) 942.2,259.9 1026.6,259.9 1199.1,432.4 1199.1,641.1 1250.4,692.4 1250.4,721.3 1268.4,739.3 v1(1269.4,739.3) ; v1(1143.3,327.9) 1231,415.6 1231,593.1 1276.2,638.3 1276.2,704.4 1269.4,711.2 v1(1269.4,739.3) ; v1(1268.8,310.4) 1237.7,341.5 1237.7,378.4 1265.35,406.05 1265.35,525.25 1307.1,567 1307.1,604.4 1301.1,610.4 1301.1,707.6 v1(1269.4,739.3) ; v1(1353.8,609.7) 1353.8,686 1300.5,739.3 v1(1269.4,739.3)
D_N: D2.2 J5.2 R40.1 | length 1214.8
  Top Layer w12: J5.2@235.48,169.61 237.4,171.53 237.4,307 237.4,761.58 361.59,885.76 799,885.76 R40.1@799,894.75
D_P: D3.2 J5.3 R41.1 R42.1 | length 1173
  Top Layer w12: J5.3@261.07,169.61 259.4,171.27 259.4,307 259.4,752.47 370.7,863.76 748.21,863.76 790.01,863.76 R41.1@799,854.78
